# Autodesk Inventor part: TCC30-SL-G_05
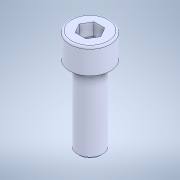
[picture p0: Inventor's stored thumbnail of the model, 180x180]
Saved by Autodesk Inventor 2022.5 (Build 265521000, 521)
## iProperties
Created: 2023-09
Part Number: TCC30-SL-G_05
Material: 一般
Document SubType Name: Modeling
Designer: ImaoCorp
Density: 1 g/cm^3
Appearance: 既定
Author: ImaoCorp
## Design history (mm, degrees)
feature "TCC30-SL-G_05"
node "ソリッド1"
